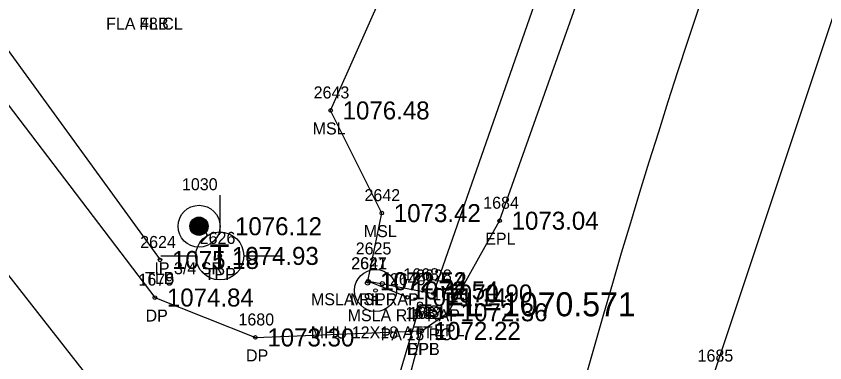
# Model space of a CAD drawing. Extents: x 1578957 to 1581675, y 1115963 to 1120391.
# Drawn here: x 1580542.9 to 1580610.3, y 1118996.5 to 1119025.4 of the extents above; entities that cross this region are included whole.
import ezdxf

# ---------------------------------------------------------------- set-up
doc = ezdxf.new("R2010")
doc.units = 0
for name, color, linetype in [('RD_EX_DR_Inlet', 7, 'Continuous'), ('RD_EX_DR_Pipe', 7, 'Continuous'), ('RD_EX_DR_Pipe_txCode', 7, 'Continuous'), ('RD_EX_Driveway', 7, 'Continuous'), ('RD_EX_Driveway_txCode', 7, 'Continuous'), ('RD_EX_DV_Prop_txCode', 7, 'Continuous'), ('RD_EX_DV_PropPin', 7, 'Continuous'), ('RD_EX_Fence_Other_txCode', 7, 'Continuous'), ('RD_EX_Misc', 7, 'Continuous'), ('RD_EX_Misc_txCode', 7, 'Continuous'), ('RD_EX_Road', 7, 'Continuous'), ('RD_EX_Road_txCode', 7, 'Continuous'), ('RD_EX_TX_Driveway_ELEV', 7, 'Continuous'), ('RD_EX_TX_DV_Prop_ELEV', 7, 'Continuous'), ('RD_EX_TX_Misc_ELEV', 7, 'Continuous'), ('RD_EX_TX_Road_ELEV', 7, 'Continuous'), ('RD_EX_TX_UT_ELEV', 7, 'Continuous'), ('RD_EX_TX_VEG_ELEV', 7, 'Continuous'), ('RD_EX_UT', 7, 'Continuous'), ('RD_EX_UT_txCode', 7, 'Continuous'), ('RD_EX_VEG', 7, 'Continuous'), ('RD_EX_VEG_txCode', 7, 'Continuous'), ('RD_HC_Cl', 7, 'Continuous'), ('RD_SMD_Locator', 7, 'Continuous'), ('RD_TX_Pipe_ElevEX', 7, 'Continuous')]:
    doc.layers.add(name, color=color, linetype=linetype)

msp = doc.modelspace()

# ---------------------------------------------------------------- linework, layer by layer
at = {"layer": 'RD_EX_DR_Inlet'}
for centre, radius in [((1580572.823, 1119002.527), 1.75), ((1580572.158, 1119003.157), 0.175), ((1580573.383, 1119003.087), 0.175), ((1580572.736, 1119001.863), 0.175)]:
    msp.add_circle(centre, radius, dxfattribs=at)
at = {"layer": 'RD_EX_DR_Pipe'}
msp.add_line((1580576.529, 1119001.375), (1580568.625, 1118974.632), dxfattribs=at)
at = {"layer": 'RD_EX_Driveway'}
for points in [[(1580510.568, 1119061.331), (1580534.626, 1119027.923), (1580554.422, 1119001.938), (1580562.8, 1118998.611), (1580576.68, 1118999.159)], [(1580572.024, 1118971.684), (1580568.59, 1118976.068), (1580551.983, 1118991.347), (1580527.809, 1119022.161), (1580503.786, 1119055.711)]]:
    msp.add_lwpolyline(points, dxfattribs=at)
at = {"layer": 'RD_EX_DV_PropPin'}
for p, q in [((1580557.37, 1119007.683), (1580557.37, 1119008.075)), ((1580557.405, 1119007.581), (1580557.405, 1119008.177)), ((1580557.44, 1119007.51), (1580557.44, 1119008.249)), ((1580557.475, 1119007.453), (1580557.475, 1119008.306)), ((1580557.51, 1119007.405), (1580557.51, 1119008.353)), ((1580557.545, 1119007.364), (1580557.545, 1119008.394)), ((1580557.58, 1119007.328), (1580557.58, 1119008.43)), ((1580557.615, 1119007.297), (1580557.615, 1119008.461)), ((1580557.65, 1119007.269), (1580557.65, 1119008.489)), ((1580557.685, 1119007.245), (1580557.685, 1119008.514)), ((1580557.72, 1119007.223), (1580557.72, 1119008.535)), ((1580557.755, 1119007.203), (1580557.755, 1119008.555)), ((1580557.79, 1119007.186), (1580557.79, 1119008.572)), ((1580557.825, 1119007.172), (1580557.825, 1119008.587)), ((1580557.86, 1119007.159), (1580557.86, 1119008.6)), ((1580557.895, 1119007.148), (1580557.895, 1119008.611)), ((1580557.93, 1119007.138), (1580557.93, 1119008.62)), ((1580557.965, 1119007.131), (1580557.965, 1119008.627)), ((1580558, 1119007.125), (1580558, 1119008.633)), ((1580558.035, 1119007.121), (1580558.035, 1119008.637)), ((1580558.07, 1119007.119), (1580558.07, 1119008.639)), ((1580558.105, 1119007.118), (1580558.105, 1119008.64)), ((1580558.14, 1119007.119), (1580558.14, 1119008.639)), ((1580558.175, 1119007.121), (1580558.175, 1119008.637)), ((1580558.21, 1119007.125), (1580558.21, 1119008.633)), ((1580558.245, 1119007.131), (1580558.245, 1119008.627)), ((1580558.28, 1119007.138), (1580558.28, 1119008.62)), ((1580558.315, 1119007.148), (1580558.315, 1119008.611)), ((1580558.35, 1119007.159), (1580558.35, 1119008.6)), ((1580558.385, 1119007.172), (1580558.385, 1119008.587)), ((1580558.42, 1119007.186), (1580558.42, 1119008.572)), ((1580558.455, 1119007.203), (1580558.455, 1119008.555)), ((1580558.49, 1119007.223), (1580558.49, 1119008.535)), ((1580558.525, 1119007.245), (1580558.525, 1119008.514)), ((1580558.56, 1119007.269), (1580558.56, 1119008.489)), ((1580558.595, 1119007.297), (1580558.595, 1119008.461)), ((1580558.63, 1119007.328), (1580558.63, 1119008.43)), ((1580558.665, 1119007.364), (1580558.665, 1119008.394)), ((1580558.7, 1119007.405), (1580558.7, 1119008.353)), ((1580558.735, 1119007.453), (1580558.735, 1119008.306)), ((1580558.77, 1119007.51), (1580558.77, 1119008.249)), ((1580558.805, 1119007.581), (1580558.805, 1119008.177)), ((1580558.84, 1119007.683), (1580558.84, 1119008.075))]:
    msp.add_line(p, q, dxfattribs=at)
for radius in [1.75, 0.761]:
    msp.add_circle((1580558.105, 1119007.879), radius, dxfattribs=at)
at = {"layer": 'RD_EX_Misc'}
for points in [[(1580575.469, 1119001.964), (1580572.192, 1119003.299), (1580573.344, 1119008.973), (1580569.078, 1119017.528), (1580583.69, 1119050.381), (1580599.817, 1119098.808), (1580624.045, 1119165.829), (1580641.396, 1119195.473), (1580666.371, 1119238.149), (1580687.021, 1119280.073), (1580703.349, 1119329.398), (1580719.477, 1119374.249), (1580736.36, 1119422.972), (1580751.158, 1119471.49)], [(1580572.228, 1119003.293), (1580577.641, 1119002.275), (1580593.887, 1119048.73), (1580611.465, 1119096.441), (1580629.396, 1119141.91), (1580650.31, 1119188.617), (1580669.532, 1119232.972), (1580689.078, 1119279.767), (1580706.148, 1119326.435), (1580722.862, 1119373.532), (1580740.07, 1119420.2), (1580755.304, 1119467.381)]]:
    msp.add_lwpolyline(points, dxfattribs=at)
at = {"layer": 'RD_EX_Road'}
for points in [[(1580561.509, 1118902.856), (1580569.284, 1118952.033), (1580572.257, 1118964.729), (1580572.024, 1118971.684), (1580570.785, 1118976.943), (1580576.68, 1118999.159), (1580578.916, 1119000.71), (1580583.17, 1119008.339), (1580597.232, 1119047.928), (1580615.21, 1119094.659), (1580634.106, 1119140.594), (1580653.543, 1119186.411), (1580672.941, 1119232.27), (1580691.817, 1119278.399), (1580709.783, 1119324.767), (1580727.167, 1119371.358), (1580744.517, 1119418.33), (1580760.444, 1119465.683)], [(1580581.375, 1118900.878), (1580589.102, 1118945.81), (1580601.044, 1118995.6), (1580615.895, 1119040.132), (1580634.471, 1119087.48), (1580652.774, 1119131.832), (1580672.351, 1119178.255), (1580691.758, 1119225.324), (1580699.116, 1119242.472), (1580700.899, 1119243.149), (1580710.457, 1119268.629), (1580709.934, 1119269.059), (1580728.392, 1119317.405), (1580728.449, 1119317.416), (1580746.747, 1119365.264), (1580763.472, 1119411.236), (1580777.809, 1119452.251), (1580781.248, 1119456.558)]]:
    msp.add_lwpolyline(points, dxfattribs=at)
at = {"layer": 'RD_EX_UT'}
for p, q in [((1580559.838, 1119010.475), (1580559.838, 1119007.406)), ((1580554.907, 1119005.421), (1580557.838, 1119005.421)), ((1580561.838, 1119005.421), (1580564.907, 1119005.421))]:
    msp.add_line(p, q, dxfattribs=at)
msp.add_circle((1580559.838, 1119005.406), 2, dxfattribs=at)
at = {"layer": 'RD_EX_VEG'}
msp.add_lwpolyline([(1580517.494, 1119056.859), (1580537.511, 1119028.94), (1580554.851, 1119005.069)], dxfattribs=at)
at = {"layer": 'RD_HC_Cl'}
msp.add_arc((1581224.951, 1118817.811), 658.967, 157.467285, 172.167204, dxfattribs=at)
at = {"layer": 'RD_SMD_Locator'}
for centre, radius in [((1580569.078, 1119017.528), 0.15), ((1580573.344, 1119008.973), 0.15), ((1580583.17, 1119008.339), 0.15), ((1580558.105, 1119007.879), 0.15), ((1580559.838, 1119005.406), 0.15), ((1580554.851, 1119005.069), 0.15), ((1580572.192, 1119003.299), 0.15), ((1580572.228, 1119003.293), 0.15), ((1580572.823, 1119002.527), 0.15), ((1580554.422, 1119001.938), 0.15), ((1580575.469, 1119001.964), 0.15), ((1580577.641, 1119002.275), 0.15), ((1580576.529, 1119001.375), 0.2), ((1580578.916, 1119000.71), 0.15), ((1580576.68, 1118999.159), 0.15), ((1580576.68, 1118999.159), 0.15), ((1580562.8, 1118998.611), 0.15)]:
    msp.add_circle(centre, radius, dxfattribs=at)

# ---------------------------------------------------------------- texts
at = {"layer": 'RD_EX_DR_Pipe_txCode'}
for s, p in [('1668', (1580575.135, 1119003.375)), ('PA 15 RC', (1580573.237, 1118998.375))]:
    msp.add_text(s, height=1, dxfattribs=at).set_placement(p)
at = {"layer": 'RD_EX_Driveway_txCode'}
for s, p in [('1679', (1580553.052, 1119002.938)), ('DP', (1580553.643, 1118999.938)), ('1680', (1580561.39, 1118999.611)), ('1681', (1580575.594, 1119000.159)), ('DPB', (1580575.428, 1118997.159)), ('DP', (1580562.02, 1118996.611))]:
    msp.add_text(s, height=1, dxfattribs=at).set_placement(p)
at = {"layer": 'RD_EX_DV_Prop_txCode'}
for s, p in [('1030', (1580556.68, 1119010.879)), ('IP 3/4 SR', (1580554.381, 1119003.879))]:
    msp.add_text(s, height=1, dxfattribs=at).set_placement(p)
at = {"layer": 'RD_EX_Fence_Other_txCode'}
for s, p in [('FLA 48 CL', (1580550.355, 1119024.263)), ('FLB', (1580553.126, 1119024.263))]:
    msp.add_text(s, height=1, dxfattribs=at).set_placement(p)
at = {"layer": 'RD_EX_Misc_txCode'}
for s, p in [('2643', (1580567.661, 1119018.528)), ('MSL', (1580567.575, 1119015.528)), ('2642', (1580571.897, 1119009.973)), ('MSL', (1580571.841, 1119006.973)), ('2627', (1580570.783, 1119004.293)), ('2641', (1580570.805, 1119004.299)), ('2628', (1580576.205, 1119003.275)), ('2640', (1580574.018, 1119002.964)), ('MSLA RIPRAP', (1580567.433, 1119001.293)), ('MSL', (1580570.689, 1119001.299)), ('MSLA RIP RAP', (1580570.49, 1118999.964)), ('MSL', (1580576.138, 1119000.275))]:
    msp.add_text(s, height=1, dxfattribs=at).set_placement(p)
at = {"layer": 'RD_EX_Road_txCode'}
for s, p in [('1684', (1580581.8, 1119009.339)), ('EPL', (1580581.965, 1119006.339)), ('1683', (1580577.546, 1119001.71)), ('1682', (1580575.31, 1119000.159)), ('EPL', (1580577.711, 1118998.71)), ('EPL', (1580575.476, 1118997.159)), ('1685', (1580599.674, 1118996.6))]:
    msp.add_text(s, height=1, dxfattribs=at).set_placement(p)
at = {"layer": 'RD_EX_TX_Driveway_ELEV'}
for s, p in [('1074.84', (1580555.422, 1119001.188)), ('1073.30', (1580563.8, 1118997.861)), ('1072.22', (1580577.68, 1118998.409))]:
    msp.add_text(s, height=1.5, dxfattribs=at).set_placement(p)
at = {"layer": 'RD_EX_TX_DV_Prop_ELEV'}
msp.add_text('1076.12', height=1.5, dxfattribs=at).set_placement((1580561.105, 1119007.129))
at = {"layer": 'RD_EX_TX_Misc_ELEV'}
for s, p in [('1076.48', (1580570.078, 1119016.778)), ('1073.42', (1580574.344, 1119008.223)), ('1072.52', (1580573.192, 1119002.549)), ('1072.54', (1580573.228, 1119002.543)), ('1071.14', (1580576.469, 1119001.214)), ('1070.90', (1580578.641, 1119001.525))]:
    msp.add_text(s, height=1.5, dxfattribs=at).set_placement(p)
at = {"layer": 'RD_EX_TX_Road_ELEV'}
for s, p in [('1073.04', (1580584.17, 1119007.589)), ('1072.36', (1580579.916, 1118999.96)), ('1072.22', (1580577.68, 1118998.409))]:
    msp.add_text(s, height=1.5, dxfattribs=at).set_placement(p)
at = {"layer": 'RD_EX_TX_UT_ELEV'}
for s, p in [('1074.93', (1580560.838, 1119004.656)), ('1072.54', (1580575.823, 1119001.777))]:
    msp.add_text(s, height=1.5, dxfattribs=at).set_placement(p)
at = {"layer": 'RD_EX_TX_VEG_ELEV'}
msp.add_text('1075.18', height=1.5, dxfattribs=at).set_placement((1580555.851, 1119004.319))
at = {"layer": 'RD_EX_UT'}
msp.add_text('T', height=2, dxfattribs=at).set_placement((1580558.989, 1119004.358))
at = {"layer": 'RD_EX_UT_txCode'}
for s, p in [('2626', (1580558.161, 1119006.406)), ('2625', (1580571.169, 1119005.527)), ('TPP', (1580558.57, 1119003.406)), ('MHU 12X18 ATT', (1580567.421, 1118998.527))]:
    msp.add_text(s, height=1, dxfattribs=at).set_placement(p)
at = {"layer": 'RD_EX_VEG_txCode'}
for s, p in [('2624', (1580553.198, 1119006.069)), ('TLB', (1580553.607, 1119003.069))]:
    msp.add_text(s, height=1, dxfattribs=at).set_placement(p)
at = {"layer": 'RD_TX_Pipe_ElevEX'}
msp.add_text('EL=1070.571', height=2, dxfattribs=at).set_placement((1580578.529, 1119000.375))

doc.saveas('drawing.dxf')
